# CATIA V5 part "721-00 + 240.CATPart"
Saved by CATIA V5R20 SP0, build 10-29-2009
Part number: 721-00 + 240
Revision: TUTTO
Definition: NON CONOSCIUTO
Nomenclature: 721-00 + 240
Source: Unknown
Bounding box of the stored display mesh (mm): x -50 to 50, y -50 to 50, z -5 to 240
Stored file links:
  C:\Users\Utente\Desktop\IO LAVORO\3D X SITO CF\X 3D SITO CF 27-09-2020\721\721-00 + 240.CATPart
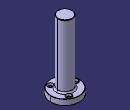
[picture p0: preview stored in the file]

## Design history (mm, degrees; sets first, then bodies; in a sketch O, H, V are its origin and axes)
Body1 "Raccordo1" (main body)
  Solid1: solid without history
